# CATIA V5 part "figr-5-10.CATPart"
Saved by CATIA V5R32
Part number: Part1
Bounding box of the stored display mesh (mm): x 0 to 150, y -70 to 70, z -150 to 69.804
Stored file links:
  D:\PROJECTS\Project 2022\CATIA V5 6R 2022\Resources\Part Files\c05_catia_v5_6r2022_prt\figr-5-10.CATPart
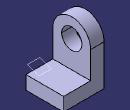
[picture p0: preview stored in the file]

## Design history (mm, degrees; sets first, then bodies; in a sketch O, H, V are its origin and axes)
Set1
  Plane1: type 2Lines, Element1 edge of Pad2, Element2 edge of Pad2
Body1 (main body)
  Sketch1 on yz-plane, origin (0, 0, 0), H (0, 1, 0), V (0, 0, 1)
    arc A1 centre (0, 0) radius 70 from (70, 0) to (-70, 0) ccw
    point P1 (70, 0)
    point P2 (-70, 0)
    line L1 (-70, 0) -> (-70, -150)
    line L2 (-70, -150) -> (70, -150)
    line L3 (70, -150) -> (70, 0)
    circle A2 centre (0, 0) radius 37.5
    radius A1 = 70
    radius A2 = 37.5
    distance O L2 = 150
    coincidence: P1 H, P2 H
    tangency: L1 A1, L3 A1
    horizontal: L2 H
  Pad1: profile Sketch1, direction (1, 0, 0), length 50
  Sketch2 on face of Pad1, origin (50, 0, 0), H (0, 1, 0), V (0, 0, 1)
    line L1 (-70, -150) -> (70, -150)
    line L2 (70, -150) -> (70, -100)
    line L3 (70, -100) -> (-70, -100)
    line L4 (-70, -100) -> (-70, -150)
    reference projected line E1 (-70, -150) -> (70, -150) from edge [face of Pad1 | face of Pad1]
    reference projected line E2 (-70, 0) -> (-70, -150) from edge [face of Pad1 | face of Pad1]
    reference projected line E3 (70, -150) -> (70, 0) from edge [face of Pad1 | face of Pad1]
    length L2 = 50
    horizontal: L1 H, L3 H
    vertical: L2 V, L4 V
    coincidence: L1 E1, E2 L4, L2 E3
  Pad2: profile Sketch2, direction (1, 0, 0), length 100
